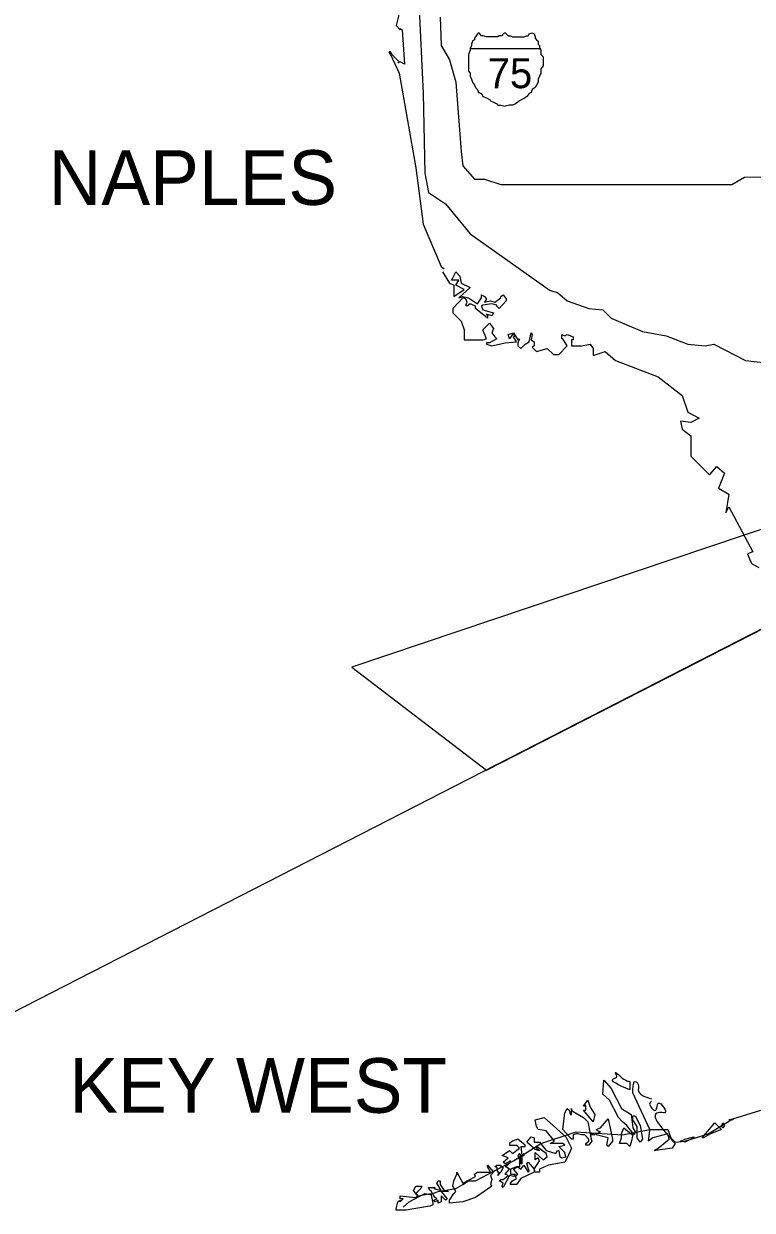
# Model space of a CAD drawing. Extents: x -827.9 to -798.1, y -2199.1 to -2182.2.
# Drawn here: x -806.228 to -805.629, y -2186.453 to -2185.475 of the extents above; entities that cross this region are included whole.
import ezdxf

# ---------------------------------------------------------------- set-up
doc = ezdxf.new("R2010")
doc.units = 0
for name, color, linetype in [('FLMap1', 7, 'Continuous'), ('FLMap2', 7, 'Continuous'), ('FLMap3', 7, 'Continuous'), ('TextMisc', 7, 'Continuous'), ('TextProjLabel', 7, 'Continuous')]:
    doc.layers.add(name, color=color, linetype=linetype)

msp = doc.modelspace()

# ---------------------------------------------------------------- linework, layer by layer
at = {"layer": 'FLMap1'}
msp.add_line((-805.86069, -2185.49575), (-805.80264, -2185.49575), dxfattribs=at)
for points in [[(-805.83191, -2185.48285), (-805.8334, -2185.48384), (-805.83439, -2185.48533), (-805.83539, -2185.48533), (-805.83688, -2185.48533), (-805.83787, -2185.48632), (-805.83886, -2185.48632), (-805.84035, -2185.48632), (-805.84283, -2185.48632), (-805.84382, -2185.48632), (-805.84481, -2185.48632), (-805.8463, -2185.48632), (-805.84729, -2185.48632), (-805.85027, -2185.48533), (-805.85126, -2185.48533), (-805.85275, -2185.48384), (-805.85374, -2185.48285), (-805.85474, -2185.48384), (-805.85622, -2185.48632), (-805.85722, -2185.48731), (-805.85722, -2185.4888), (-805.85871, -2185.48979), (-805.8597, -2185.49227), (-805.8597, -2185.49327), (-805.86069, -2185.49575), (-805.86069, -2185.49724), (-805.86218, -2185.50071), (-805.86218, -2185.50269), (-805.86218, -2185.50517), (-805.86218, -2185.50765), (-805.86218, -2185.51013), (-805.86218, -2185.51261), (-805.86218, -2185.5146), (-805.86069, -2185.51609), (-805.86069, -2185.51857), (-805.8597, -2185.52105), (-805.85871, -2185.52353), (-805.85722, -2185.52601), (-805.85622, -2185.52799), (-805.85474, -2185.52948), (-805.85374, -2185.53196), (-805.85126, -2185.53296), (-805.85027, -2185.53544), (-805.84729, -2185.53643), (-805.84481, -2185.53792), (-805.84382, -2185.53891), (-805.84134, -2185.5399), (-805.83886, -2185.54139), (-805.83787, -2185.54238), (-805.83539, -2185.54238), (-805.83191, -2185.54337)], [(-805.83191, -2185.48285), (-805.83092, -2185.48384), (-805.82943, -2185.48533), (-805.82844, -2185.48533), (-805.82745, -2185.48533), (-805.82596, -2185.48632), (-805.82348, -2185.48632), (-805.82249, -2185.48632), (-805.8215, -2185.48632), (-805.82001, -2185.48632), (-805.81902, -2185.48632), (-805.81802, -2185.48632), (-805.81653, -2185.48632), (-805.81405, -2185.48533), (-805.81306, -2185.48533), (-805.81207, -2185.48384), (-805.80959, -2185.48285), (-805.8081, -2185.48384), (-805.80711, -2185.48632), (-805.80711, -2185.48731), (-805.80612, -2185.4888), (-805.80463, -2185.48979), (-805.80463, -2185.49227), (-805.80364, -2185.49327), (-805.80364, -2185.49575), (-805.80264, -2185.49724), (-805.80264, -2185.50071), (-805.80066, -2185.50269), (-805.80066, -2185.50517), (-805.80066, -2185.50765), (-805.80066, -2185.51013), (-805.80264, -2185.51261), (-805.80264, -2185.5146), (-805.80264, -2185.51609), (-805.80364, -2185.51857), (-805.80463, -2185.52105), (-805.80463, -2185.52353), (-805.80612, -2185.52601), (-805.80711, -2185.52799), (-805.80959, -2185.52948), (-805.81058, -2185.53196), (-805.81207, -2185.53296), (-805.81405, -2185.53544), (-805.81554, -2185.53643), (-805.81802, -2185.53792), (-805.82001, -2185.53891), (-805.8215, -2185.5399), (-805.82348, -2185.54139), (-805.82596, -2185.54238), (-805.82844, -2185.54238), (-805.83191, -2185.54337)]]:
    msp.add_lwpolyline(points, dxfattribs=at)
at = {"layer": 'FLMap2'}
for points in [[(-805.90286, -2185.45755), (-805.89939, -2185.53296), (-805.8979, -2185.59844), (-805.89492, -2185.61432), (-805.88103, -2185.62375), (-805.86069, -2185.64855), (-805.7947, -2185.69519), (-805.78875, -2185.69668), (-805.78081, -2185.70362), (-805.76295, -2185.71007), (-805.75154, -2185.71106), (-805.7446, -2185.71801), (-805.7188, -2185.72893), (-805.69945, -2185.7324), (-805.68159, -2185.73934), (-805.6672, -2185.74083), (-805.66026, -2185.73934), (-805.63396, -2185.75274), (-805.4881, -2185.76961)], [(-805.91923, -2185.46697), (-805.92171, -2185.47689), (-805.91824, -2185.48037), (-805.91824, -2185.47937), (-805.91824, -2185.47937), (-805.91675, -2185.48037), (-805.91477, -2185.50865), (-805.91824, -2185.50666), (-805.92022, -2185.50765), (-805.92022, -2185.50765), (-805.91923, -2185.50666), (-805.92519, -2185.50071), (-805.92618, -2185.49823), (-805.92618, -2185.49823), (-805.92767, -2185.49922), (-805.92618, -2185.50071), (-805.91923, -2185.51609)], [(-805.91923, -2185.51609), (-805.90534, -2185.59398), (-805.89939, -2185.64062), (-805.8845, -2185.67534), (-805.88202, -2185.67733)], [(-805.88351, -2185.67981), (-805.87756, -2185.68924), (-805.87408, -2185.69072), (-805.87408, -2185.70015), (-805.86565, -2185.6942), (-805.8726, -2185.69072), (-805.87012, -2185.68675), (-805.87607, -2185.68675), (-805.87508, -2185.68477), (-805.8726, -2185.67981), (-805.86912, -2185.68328), (-805.86813, -2185.68924), (-805.86069, -2185.69271), (-805.87012, -2185.70114), (-805.86664, -2185.70015), (-805.86218, -2185.70114), (-805.85474, -2185.7061), (-805.85126, -2185.70114), (-805.85126, -2185.69866), (-805.84878, -2185.70015), (-805.84729, -2185.70213), (-805.84878, -2185.70462), (-805.84382, -2185.70362), (-805.84035, -2185.70462), (-805.83539, -2185.70114), (-805.83539, -2185.70015), (-805.8334, -2185.69866), (-805.83092, -2185.70213), (-805.83092, -2185.70362), (-805.83688, -2185.71007), (-805.83886, -2185.70809), (-805.83886, -2185.7071), (-805.84283, -2185.7061), (-805.85027, -2185.7071), (-805.85126, -2185.70809), (-805.85027, -2185.71106), (-805.84134, -2185.71355), (-805.84283, -2185.71603), (-805.84729, -2185.71454), (-805.8463, -2185.71603), (-805.8463, -2185.71801), (-805.8463, -2185.71801), (-805.85622, -2185.71007), (-805.85622, -2185.70809), (-805.86069, -2185.7061), (-805.86317, -2185.70809), (-805.86416, -2185.7071), (-805.86317, -2185.70462)], [(-805.86317, -2185.70462), (-805.86416, -2185.70213), (-805.86664, -2185.70114), (-805.87012, -2185.70462), (-805.87508, -2185.71007), (-805.87508, -2185.71355), (-805.87508, -2185.71355), (-805.86813, -2185.72049)], [(-805.86813, -2185.72049), (-805.86565, -2185.72744), (-805.86565, -2185.73587), (-805.85027, -2185.73587), (-805.84729, -2185.73488), (-805.85027, -2185.72744), (-805.84481, -2185.72198), (-805.84134, -2185.72644), (-805.84283, -2185.72992), (-805.84035, -2185.73339), (-805.83886, -2185.73488), (-805.84481, -2185.73835), (-805.84729, -2185.73835), (-805.84729, -2185.73934), (-805.84283, -2185.74083), (-805.83191, -2185.73835), (-805.82249, -2185.73736), (-805.82497, -2185.73339), (-805.82348, -2185.7324), (-805.82596, -2185.73141), (-805.82844, -2185.73488), (-805.82943, -2185.73141), (-805.82497, -2185.72992), (-805.8215, -2185.73587), (-805.82001, -2185.73488), (-805.8215, -2185.73835), (-805.8215, -2185.74083), (-805.81902, -2185.74282), (-805.81554, -2185.73934), (-805.81207, -2185.73736), (-805.81058, -2185.72992), (-805.80959, -2185.73141), (-805.81058, -2185.73587), (-805.8081, -2185.73736), (-805.8081, -2185.74083), (-805.80959, -2185.74182), (-805.80612, -2185.7453), (-805.79719, -2185.74282), (-805.79222, -2185.74778), (-805.78776, -2185.74778), (-805.78081, -2185.74083), (-805.78429, -2185.73488), (-805.78528, -2185.73488), (-805.78528, -2185.73141), (-805.7828, -2185.7324), (-805.78081, -2185.73141), (-805.77585, -2185.73339), (-805.77585, -2185.73587), (-805.77734, -2185.73587), (-805.77734, -2185.74083), (-805.77337, -2185.74083)], [(-805.77337, -2185.74083), (-805.76891, -2185.74083), (-805.76196, -2185.73934), (-805.75948, -2185.74282), (-805.75948, -2185.74877), (-805.74956, -2185.7453), (-805.74112, -2185.75274), (-805.7059, -2185.76613)], [(-805.7059, -2185.76613), (-805.68605, -2185.78151), (-805.68159, -2185.79541), (-805.67216, -2185.80037), (-805.67911, -2185.80384), (-805.68754, -2185.80285), (-805.68605, -2185.8093), (-805.67911, -2185.81475), (-805.67911, -2185.83162), (-805.66373, -2185.847), (-805.65777, -2185.84006), (-805.65132, -2185.84551), (-805.65629, -2185.85792), (-805.64785, -2185.86288), (-805.65033, -2185.87826), (-805.64785, -2185.8733), (-805.62801, -2185.91051), (-805.63247, -2185.912), (-805.629, -2185.91993), (-805.62305, -2185.92341)], [(-805.72574, -2186.39076), (-805.7317, -2186.38282), (-805.73517, -2186.37984), (-805.73864, -2186.37637), (-805.74608, -2186.36198), (-805.75154, -2186.35702), (-805.75055, -2186.34561), (-805.7446, -2186.35255), (-805.73616, -2186.36893), (-805.72822, -2186.37389), (-805.72674, -2186.3848), (-805.72475, -2186.38827), (-805.72574, -2186.39076)], [(-805.69201, -2186.3977), (-805.69449, -2186.40167), (-805.70788, -2186.40365), (-805.70937, -2186.40365), (-805.7059, -2186.40167), (-805.69697, -2186.39423), (-805.69796, -2186.38976), (-805.71036, -2186.39324), (-805.71384, -2186.39572), (-805.71284, -2186.38728), (-805.71284, -2186.38629), (-805.72674, -2186.35603), (-805.72674, -2186.35355)], [(-805.91576, -2186.45029), (-805.9108, -2186.44583), (-805.8979, -2186.43888), (-805.89393, -2186.43987), (-805.88698, -2186.43739), (-805.8726, -2186.43491), (-805.86664, -2186.43144), (-805.86218, -2186.42846), (-805.85622, -2186.42846), (-805.82497, -2186.41209), (-805.80264, -2186.3977), (-805.77337, -2186.38827), (-805.73517, -2186.39076), (-805.71284, -2186.38629), (-805.69796, -2186.38629), (-805.69548, -2186.39324), (-805.69201, -2186.39671), (-805.68407, -2186.39572), (-805.66472, -2186.38976), (-805.64438, -2186.37736), (-805.6027, -2186.36446)], [(-805.76742, -2186.36694), (-805.76643, -2186.36545), (-805.76395, -2186.36198), (-805.76196, -2186.36793), (-805.75799, -2186.37389), (-805.75948, -2186.37984), (-805.76742, -2186.37041), (-805.76543, -2186.37041), (-805.76543, -2186.36694)], [(-805.76543, -2186.36694), (-805.76643, -2186.36545), (-805.76742, -2186.36694)], [(-805.77734, -2186.39423), (-805.78429, -2186.38629), (-805.7828, -2186.3724), (-805.78081, -2186.36893), (-805.77933, -2186.37041), (-805.77833, -2186.37389), (-805.77734, -2186.37389), (-805.77734, -2186.36893), (-805.77734, -2186.37041), (-805.77585, -2186.37141), (-805.76742, -2186.37637), (-805.76395, -2186.37984), (-805.76196, -2186.38976), (-805.75948, -2186.38976), (-805.75799, -2186.39076), (-805.76196, -2186.39076), (-805.76047, -2186.39572)], [(-805.76643, -2186.36694), (-805.76742, -2186.36694)], [(-805.72326, -2186.39324), (-805.72326, -2186.38381), (-805.72674, -2186.37835), (-805.72674, -2186.37488), (-805.72475, -2186.37488), (-805.72078, -2186.38282), (-805.7188, -2186.39423), (-805.72078, -2186.39671), (-805.72326, -2186.39324)], [(-805.81405, -2186.39671), (-805.81058, -2186.39224), (-805.8081, -2186.39324), (-805.8081, -2186.39671), (-805.80364, -2186.39671), (-805.79818, -2186.40365), (-805.79024, -2186.40614), (-805.78875, -2186.40365), (-805.78776, -2186.40365), (-805.78677, -2186.40862), (-805.78528, -2186.40961), (-805.78181, -2186.40862), (-805.7828, -2186.40514), (-805.78776, -2186.40018), (-805.7828, -2186.39919), (-805.78429, -2186.3977), (-805.7947, -2186.3977), (-805.7947, -2186.3977), (-805.79123, -2186.39572), (-805.79818, -2186.38728), (-805.80463, -2186.38629), (-805.80612, -2186.38381), (-805.80711, -2186.37835), (-805.79967, -2186.37637), (-805.78181, -2186.39224), (-805.77734, -2186.40167), (-805.78081, -2186.40961), (-805.7828, -2186.41308), (-805.79619, -2186.41556), (-805.80364, -2186.41903), (-805.80364, -2186.42151), (-805.80711, -2186.42151), (-805.8081, -2186.41903)], [(-805.757, -2186.38629), (-805.75353, -2186.3848), (-805.74708, -2186.37736), (-805.7436, -2186.39423), (-805.7436, -2186.39572), (-805.74708, -2186.40018), (-805.74807, -2186.39919), (-805.74708, -2186.39324), (-805.757, -2186.39076), (-805.757, -2186.38976), (-805.75353, -2186.38827), (-805.75353, -2186.38827), (-805.75601, -2186.38728), (-805.757, -2186.38629)], [(-805.73765, -2186.3977), (-805.73616, -2186.39324), (-805.73616, -2186.38976), (-805.73418, -2186.3848), (-805.72822, -2186.38976), (-805.72674, -2186.39076), (-805.72822, -2186.39671), (-805.72922, -2186.40018), (-805.7317, -2186.3977), (-805.73765, -2186.3977)], [(-805.66968, -2186.39324), (-805.65926, -2186.38083)], [(-805.65926, -2186.38083), (-805.65381, -2186.38629), (-805.66274, -2186.38976), (-805.66274, -2186.38976), (-805.66869, -2186.39324), (-805.66968, -2186.39324)], [(-805.65381, -2186.38381), (-805.65281, -2186.38083)], [(-805.65281, -2186.38083), (-805.65132, -2186.38282), (-805.65281, -2186.3848), (-805.65381, -2186.38381)], [(-805.64785, -2186.37835), (-805.64438, -2186.37736), (-805.64438, -2186.37835)], [(-805.64438, -2186.37835), (-805.64686, -2186.37835), (-805.64785, -2186.37835)], [(-805.81902, -2186.40018), (-805.81554, -2186.40018), (-805.81554, -2186.39919), (-805.8215, -2186.39423), (-805.82596, -2186.39572), (-805.82844, -2186.3977), (-805.82844, -2186.39919), (-805.82249, -2186.39919), (-805.82001, -2186.40167)], [(-805.76047, -2186.39572), (-805.76295, -2186.39919), (-805.76543, -2186.39919), (-805.76543, -2186.3977), (-805.76295, -2186.39572), (-805.76295, -2186.39423), (-805.76643, -2186.39076), (-805.76891, -2186.39076), (-805.77238, -2186.38976), (-805.77337, -2186.38976), (-805.77585, -2186.39076), (-805.77585, -2186.39423), (-805.77734, -2186.39423)], [(-805.68754, -2186.39572), (-805.68407, -2186.39423), (-805.67663, -2186.39224)], [(-805.67663, -2186.39224), (-805.67663, -2186.39324), (-805.68407, -2186.39671), (-805.68754, -2186.39572)], [(-805.81902, -2186.40018), (-805.81802, -2186.40762), (-805.81653, -2186.40614), (-805.81653, -2186.40762), (-805.81802, -2186.40862), (-805.81802, -2186.41308), (-805.81802, -2186.41457), (-805.81902, -2186.41457), (-805.81902, -2186.40961), (-805.82001, -2186.40961), (-805.82001, -2186.40862), (-805.81902, -2186.40762), (-805.82001, -2186.40614), (-805.8215, -2186.40762), (-805.82001, -2186.4111), (-805.82001, -2186.41705), (-805.82249, -2186.41705), (-805.82745, -2186.41903), (-805.82745, -2186.423), (-805.82348, -2186.423), (-805.82497, -2186.42499), (-805.82844, -2186.424), (-805.8334, -2186.43392), (-805.83439, -2186.43293), (-805.8334, -2186.43045), (-805.83688, -2186.42846), (-805.83539, -2186.42747), (-805.8334, -2186.42747), (-805.82943, -2186.424), (-805.83191, -2186.423), (-805.82844, -2186.41903)], [(-805.82844, -2186.41903), (-805.83092, -2186.41705), (-805.83191, -2186.41705), (-805.83191, -2186.41705), (-805.82745, -2186.41308), (-805.82745, -2186.41209), (-805.83191, -2186.41457), (-805.8334, -2186.41308), (-805.82943, -2186.40961), (-805.83439, -2186.40762), (-805.82844, -2186.40365), (-805.82596, -2186.40614), (-805.82001, -2186.40167)], [(-805.80711, -2186.42151), (-805.8081, -2186.41903), (-805.80364, -2186.41209), (-805.80463, -2186.40961), (-805.80711, -2186.4111), (-805.80711, -2186.40514), (-805.80066, -2186.4111), (-805.79719, -2186.40862), (-805.79818, -2186.40614), (-805.80612, -2186.40018), (-805.80612, -2186.40167), (-805.80364, -2186.40365), (-805.80463, -2186.40365), (-805.80711, -2186.40266), (-805.81405, -2186.39671)], [(-805.82745, -2186.43144), (-805.82745, -2186.43045), (-805.82596, -2186.42846), (-805.82249, -2186.42648), (-805.82348, -2186.42499), (-805.8215, -2186.423), (-805.82497, -2186.41903), (-805.8215, -2186.41705), (-805.81902, -2186.41903), (-805.81653, -2186.41556), (-805.81306, -2186.42151), (-805.81207, -2186.42052), (-805.81405, -2186.41457), (-805.81306, -2186.41308), (-805.8081, -2186.41903), (-805.8081, -2186.42151), (-805.81902, -2186.42648), (-805.82249, -2186.43144), (-805.82745, -2186.43144), (-805.82745, -2186.43045)], [(-805.87756, -2186.44434), (-805.87408, -2186.43888), (-805.8726, -2186.43739), (-805.87508, -2186.43293), (-805.87408, -2186.42846), (-805.8716, -2186.423), (-805.8716, -2186.42151), (-805.86664, -2186.43045), (-805.85622, -2186.42499), (-805.85722, -2186.423), (-805.85474, -2186.42151), (-805.84382, -2186.42151), (-805.8463, -2186.41705), (-805.8463, -2186.41556), (-805.84134, -2186.42151), (-805.84382, -2186.424), (-805.84283, -2186.42747)], [(-805.83886, -2186.41705), (-805.84035, -2186.41705), (-805.83886, -2186.41556), (-805.83539, -2186.41556), (-805.83539, -2186.41705), (-805.83439, -2186.41705), (-805.8334, -2186.41804), (-805.83439, -2186.41903), (-805.83539, -2186.42151), (-805.83787, -2186.424), (-805.83787, -2186.424), (-805.83688, -2186.42151)], [(-805.83787, -2186.42151), (-805.83886, -2186.41705), (-805.83886, -2186.41705)], [(-805.83688, -2186.42151), (-805.83787, -2186.42151), (-805.83787, -2186.42151)], [(-805.92022, -2186.44583), (-805.91824, -2186.44434), (-805.91824, -2186.44583), (-805.91576, -2186.44334), (-805.91824, -2186.44334), (-805.91824, -2186.44086), (-805.90534, -2186.44235), (-805.90385, -2186.44086), (-805.90534, -2186.43888), (-805.90733, -2186.4364), (-805.90534, -2186.43293), (-805.90038, -2186.43293), (-805.90137, -2186.43491), (-805.90534, -2186.43888), (-805.90385, -2186.44086), (-805.89294, -2186.43888), (-805.89145, -2186.44682), (-805.89145, -2186.44831), (-805.89393, -2186.4493), (-805.90881, -2186.45178), (-805.91328, -2186.45277), (-805.92171, -2186.45277), (-805.92171, -2186.45178)], [(-805.88946, -2186.44583), (-805.89046, -2186.44434), (-805.88798, -2186.44334), (-805.88946, -2186.44235), (-805.89046, -2186.44086), (-805.89294, -2186.4364), (-805.89393, -2186.4364), (-805.89492, -2186.43392), (-805.88946, -2186.43392), (-805.89046, -2186.43491), (-805.8845, -2186.4364), (-805.88798, -2186.43045), (-805.88698, -2186.42846), (-805.8855, -2186.42846), (-805.8855, -2186.43144), (-805.88202, -2186.4364), (-805.87954, -2186.4364), (-805.87855, -2186.43739), (-805.8845, -2186.43739), (-805.87954, -2186.44334), (-805.88103, -2186.44434), (-805.8845, -2186.44086)], [(-805.84283, -2186.42747), (-805.84382, -2186.43144), (-805.84283, -2186.43293), (-805.84283, -2186.43293), (-805.85622, -2186.44235), (-805.86664, -2186.44583), (-805.87756, -2186.44682), (-805.87756, -2186.44434)], [(-805.8845, -2186.44086), (-805.8845, -2186.44583), (-805.88698, -2186.44682), (-805.88698, -2186.44434), (-805.88946, -2186.44583)], [(-805.92171, -2186.45178), (-805.92022, -2186.44583)]]:
    msp.add_lwpolyline(points, dxfattribs=at)
for points in [[(-805.72922, -2186.35355), (-805.74212, -2186.34412), (-805.74013, -2186.34313), (-805.74112, -2186.33965), (-805.73269, -2186.34561), (-805.72922, -2186.3466)], [(-805.72674, -2186.35355), (-805.72475, -2186.3466), (-805.72227, -2186.34908), (-805.72227, -2186.35355), (-805.71136, -2186.36099)], [(-805.72922, -2186.3466), (-805.72922, -2186.35255), (-805.72922, -2186.35355)], [(-805.71136, -2186.36297), (-805.71284, -2186.36446), (-805.70788, -2186.37041), (-805.7059, -2186.36446), (-805.70044, -2186.3724), (-805.70143, -2186.3724), (-805.7059, -2186.3724), (-805.69201, -2186.3977)]]:
    msp.add_spline(points, degree=3, dxfattribs=at)
at = {"layer": 'FLMap3'}
for points in [[(-805.8855, -2185.46995), (-805.8845, -2185.49327), (-805.87756, -2185.50517), (-805.8726, -2185.52353), (-805.86813, -2185.58058), (-805.86664, -2185.59249), (-805.85722, -2185.60341), (-805.84878, -2185.60341), (-805.83539, -2185.60787)], [(-805.83539, -2185.60787), (-805.64537, -2185.60787), (-805.63495, -2185.60192), (-805.46925, -2185.60093), (-805.45436, -2185.60093), (-805.38193, -2185.61531), (-805.26187, -2185.61531)]]:
    msp.add_lwpolyline(points, dxfattribs=at)
at = {"layer": 'TextProjLabel'}
for p, q in [((-805.15322, -2185.73436), (-806.36333, -2186.35447)), ((-805.15322, -2185.73436), (-805.95819, -2186.00545)), ((-805.84732, -2186.0902), (-805.15322, -2185.73436)), ((-805.95819, -2186.00545), (-805.84732, -2186.0902))]:
    msp.add_line(p, q, dxfattribs=at)

# ---------------------------------------------------------------- texts
at = {"layer": 'TextMisc'}
for s, height, p in [('75', 0.024695, (-805.84632, -2185.52849)), ('NAPLES', 0.045, (-806.2077, -2185.62462)), ('KEY WEST', 0.045, (-806.19058, -2186.37248))]:
    msp.add_text(s, height=height, dxfattribs=at).set_placement(p)

doc.saveas('drawing.dxf')
